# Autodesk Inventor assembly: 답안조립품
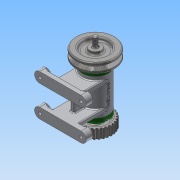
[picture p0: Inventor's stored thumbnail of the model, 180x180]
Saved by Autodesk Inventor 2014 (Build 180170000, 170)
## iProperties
Created: 2015-11
Part Number: 답안조립품
Document SubType Name: Assembly
Designer: 103-17
Author: 103-17
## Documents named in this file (13)
- C:\Users\103-17\Desktop\451110V1018\답안조립품.iam
- C:\Users\103-17\Desktop\451110V1018\1-본체.ipt
- C:\Users\103-17\Desktop\451110V1018\베어링 15 x 32 x 9.ipt
- C:\Users\103-17\Desktop\451110V1018\축.ipt
- C:\Users\103-17\Desktop\451110V1018\키 3 x 3 x 12.ipt
- C:\Users\103-17\Desktop\451110V1018\커버.ipt
- C:\Users\103-17\Desktop\451110V1018\오일 실 15 25 7.ipt
- C:\Users\103-17\Desktop\451110V1018\볼트 M4 x 12.ipt
- C:\Users\103-17\Desktop\451110V1018\스퍼기어.ipt
- C:\Users\103-17\Desktop\451110V1018\와셔 8x17.ipt
- C:\Users\103-17\Desktop\451110V1018\스프링와셔 8.ipt
- C:\Users\103-17\Desktop\451110V1018\너트 M 8.ipt
- C:\Users\103-17\Desktop\451110V1018\V벨트풀리.ipt
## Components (12 placed, 4 different names)
1. 1-본체:1
2. KS B 2023 6002 - 15 x 32 x 9:1
3. KS B 2023 6002 - 15 x 32 x 9:2
4. V벨트풀리:1 — 플러쉬:2, 각도:6
5. ISO 4762 M4 x 12:1
6. ISO 4762 M4 x 12:3
7. ISO 4762 M4 x 12:4
8. ISO 4762 M4 x 12:5
9. ISO 4762 M4 x 12:2
10. ISO 4762 M4 x 12:6
11. ISO 4762 M4 x 12:7
12. ISO 4762 M4 x 12:8
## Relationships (2: Flush 1, Angle 1)
- 플러쉬:2 [Flush]: V벨트풀리:1
- 각도:6 [Angle]: V벨트풀리:1
